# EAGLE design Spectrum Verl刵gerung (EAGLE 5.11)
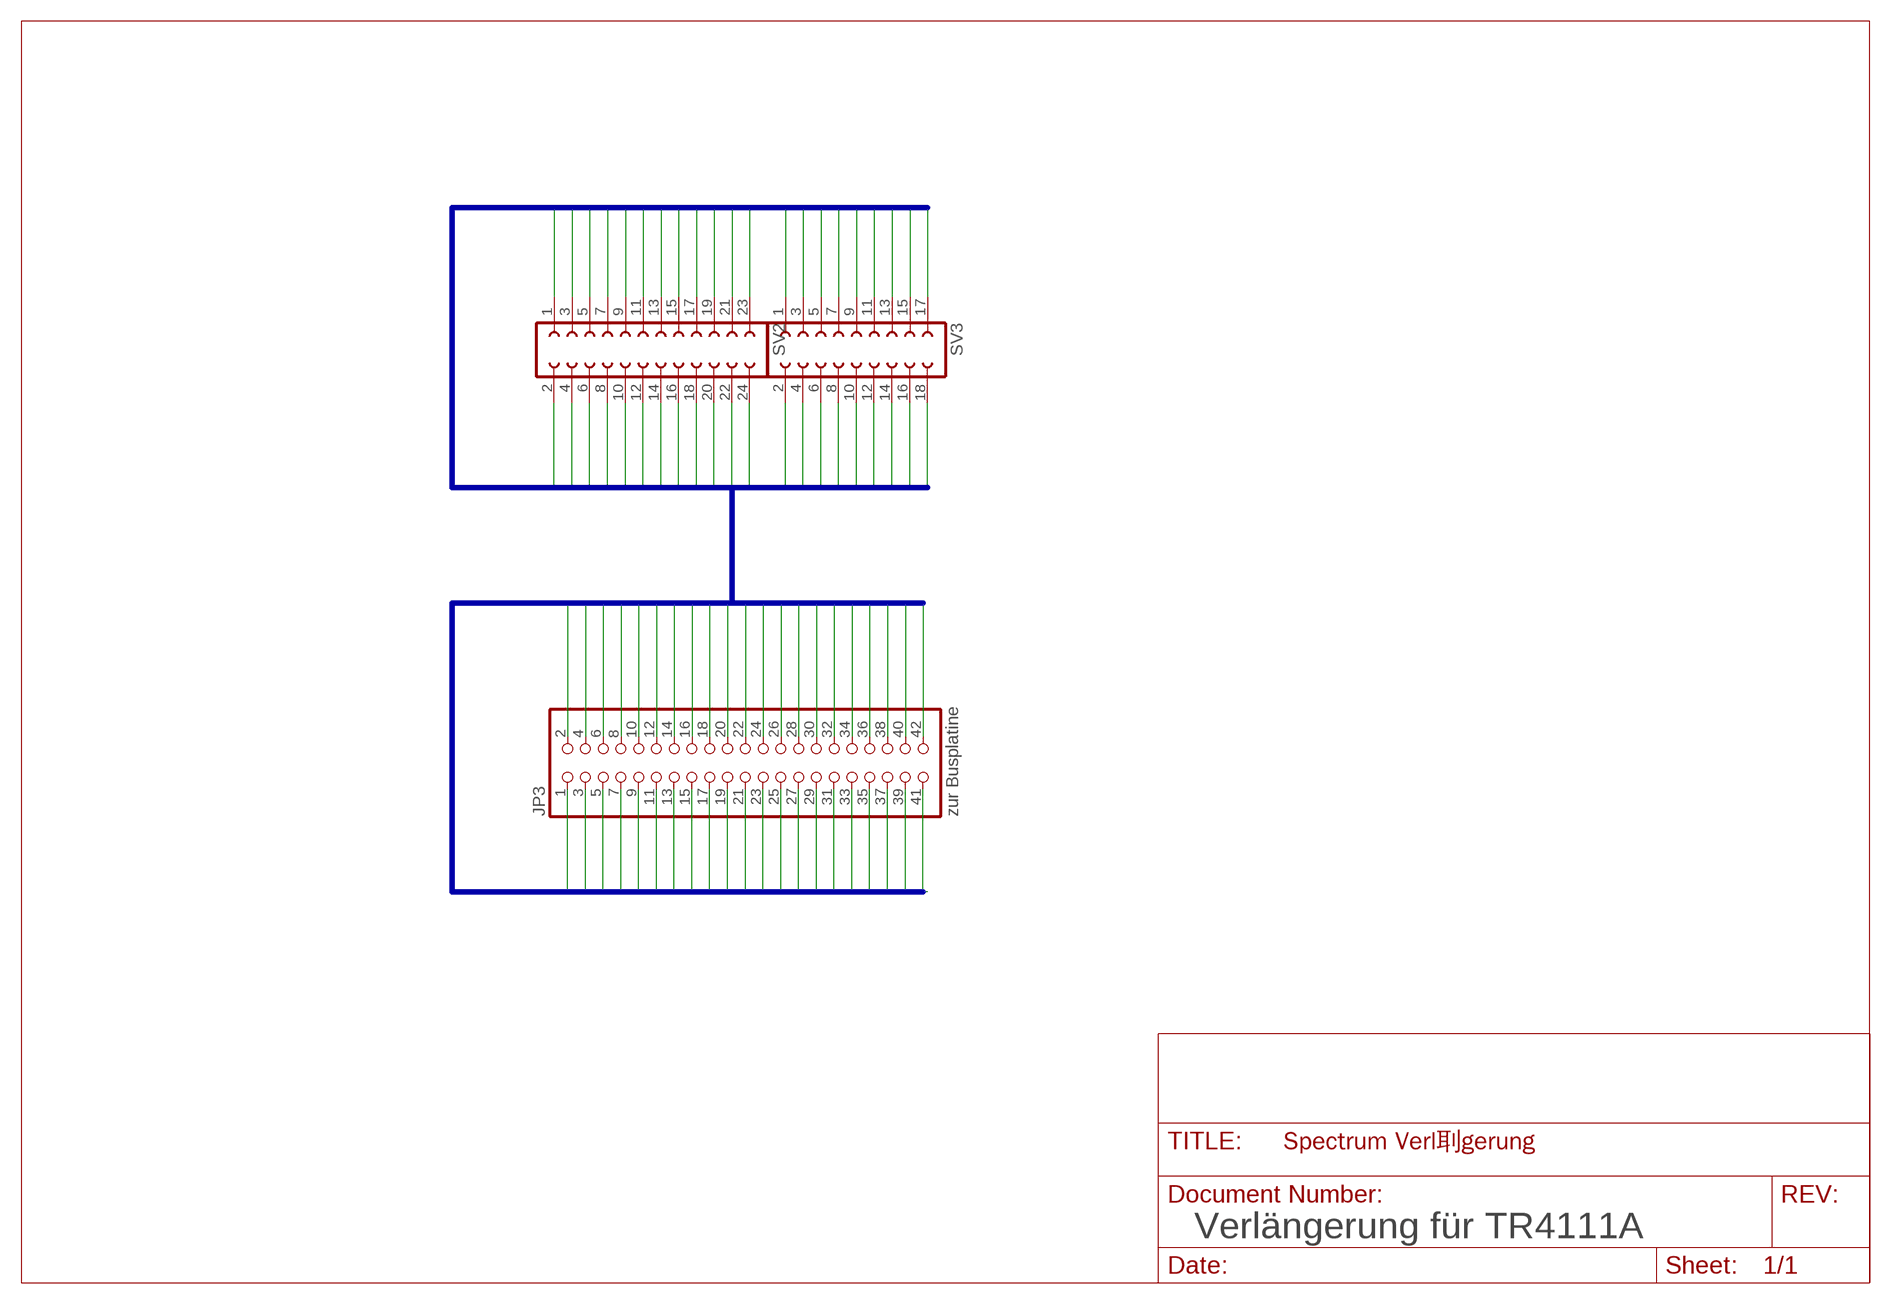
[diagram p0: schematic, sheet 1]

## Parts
JP3  zur Busplatine  PINHD-2X21_2.54-90°  [2X21/90]
SV2  FE12-2W  [FE12-2W]
SV3  FE09-2W  [FE09-2W]

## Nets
A1: JP3.1 SV2.1
A2: JP3.2 SV2.2
A3: JP3.3 SV2.3
A4: JP3.4 SV2.4
A5: JP3.5 SV2.5
A6: JP3.6 SV2.6
A7: JP3.7 SV2.7
A8: JP3.8 SV2.8
A9: JP3.9 SV2.9
A10: JP3.10 SV2.10
A11: JP3.11 SV2.11
A12: JP3.12 SV2.12
A13: JP3.13 SV2.13
A14: JP3.14 SV2.14
A15: JP3.15 SV2.15
A16: JP3.16 SV2.16
A17: JP3.17 SV2.17
A18: JP3.18 SV2.18
A19: JP3.19 SV2.19
A20: JP3.20 SV2.20
A21: JP3.21 SV2.21
A22: JP3.22 SV2.22
A23: JP3.23 SV2.23
A24: JP3.24 SV2.24
A25: JP3.25 SV3.1
A26: JP3.26 SV3.2
A27: JP3.27 SV3.3
A28: JP3.28 SV3.4
A29: JP3.29 SV3.5
A30: JP3.30 SV3.6
A31: JP3.31 SV3.7
A32: JP3.32 SV3.8
A33: JP3.33 SV3.9
A34: JP3.34 SV3.10
A35: JP3.35 SV3.11
A36: JP3.36 SV3.12
A37: JP3.37 SV3.13
A38: JP3.38 SV3.14
A39: JP3.39 SV3.15
A40: JP3.40 SV3.16
A41: JP3.41 SV3.17
A42: JP3.42 SV3.18

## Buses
A[1..42]

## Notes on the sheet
- Verlängerung für TR4111A

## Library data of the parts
JP3 = pinhead-2:PINHD-2X21: PIN HEADER
SV2 = con-lsta:FE12-2W: FEMALE HEADER
SV3 = con-lsta:FE09-2W: FEMALE HEADER

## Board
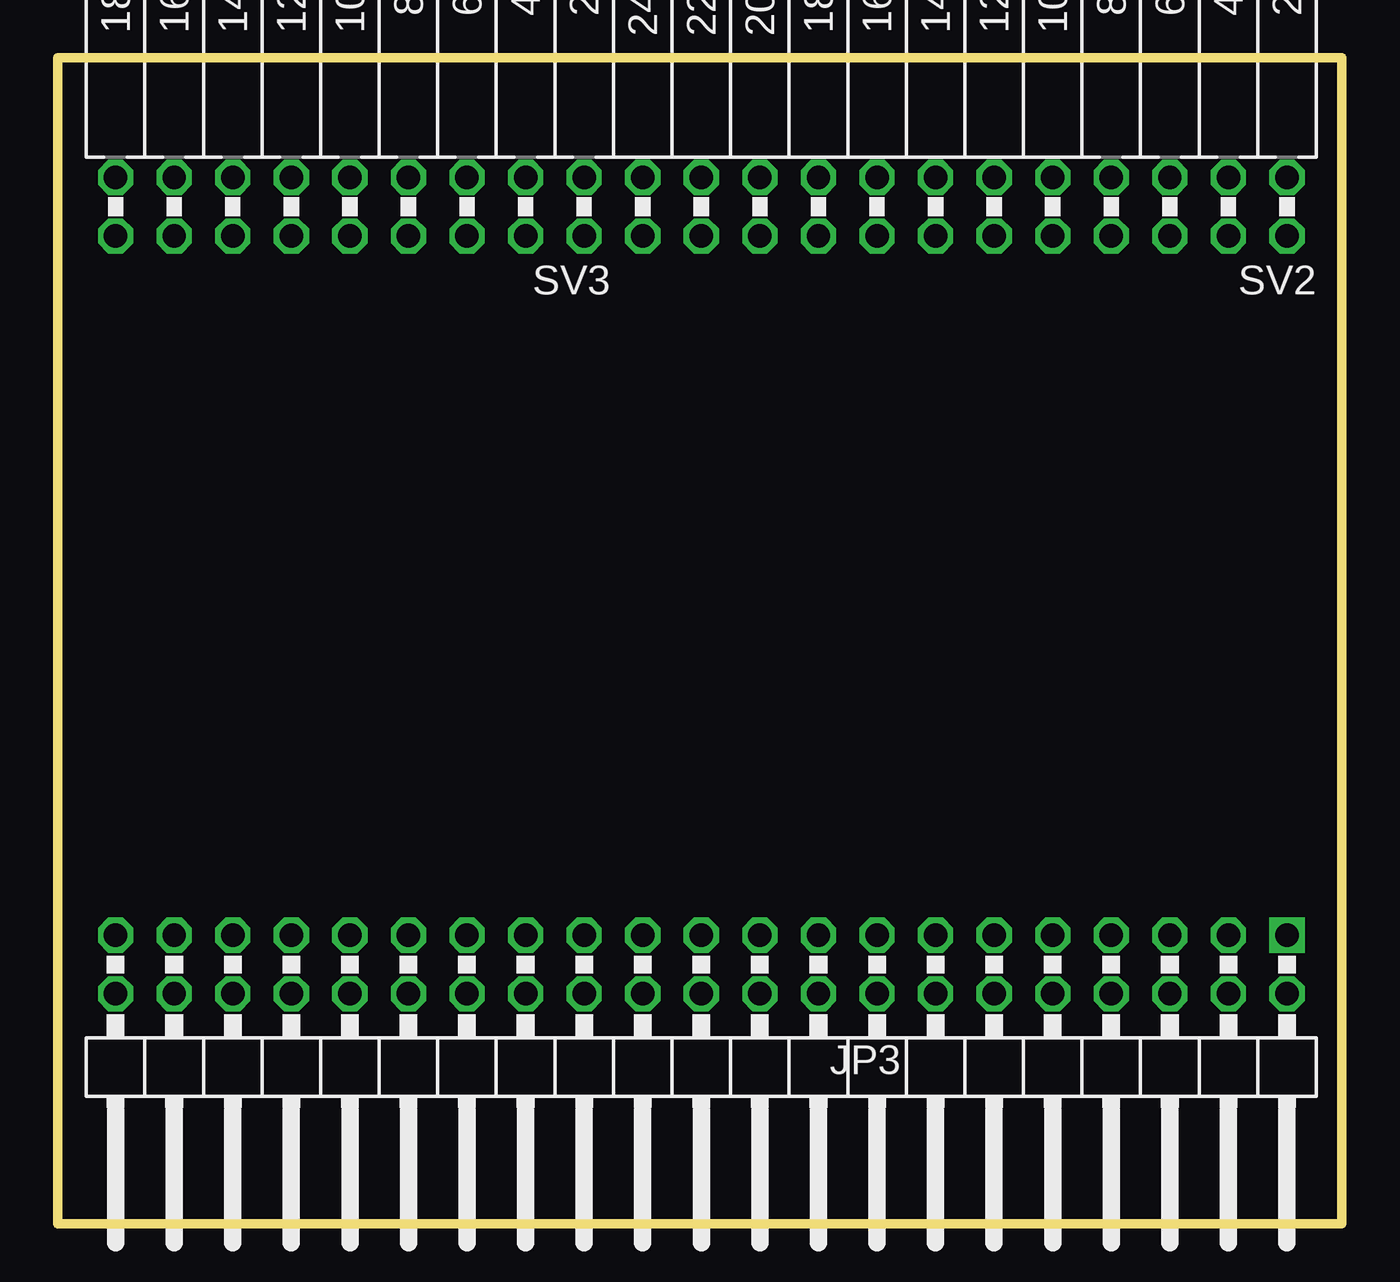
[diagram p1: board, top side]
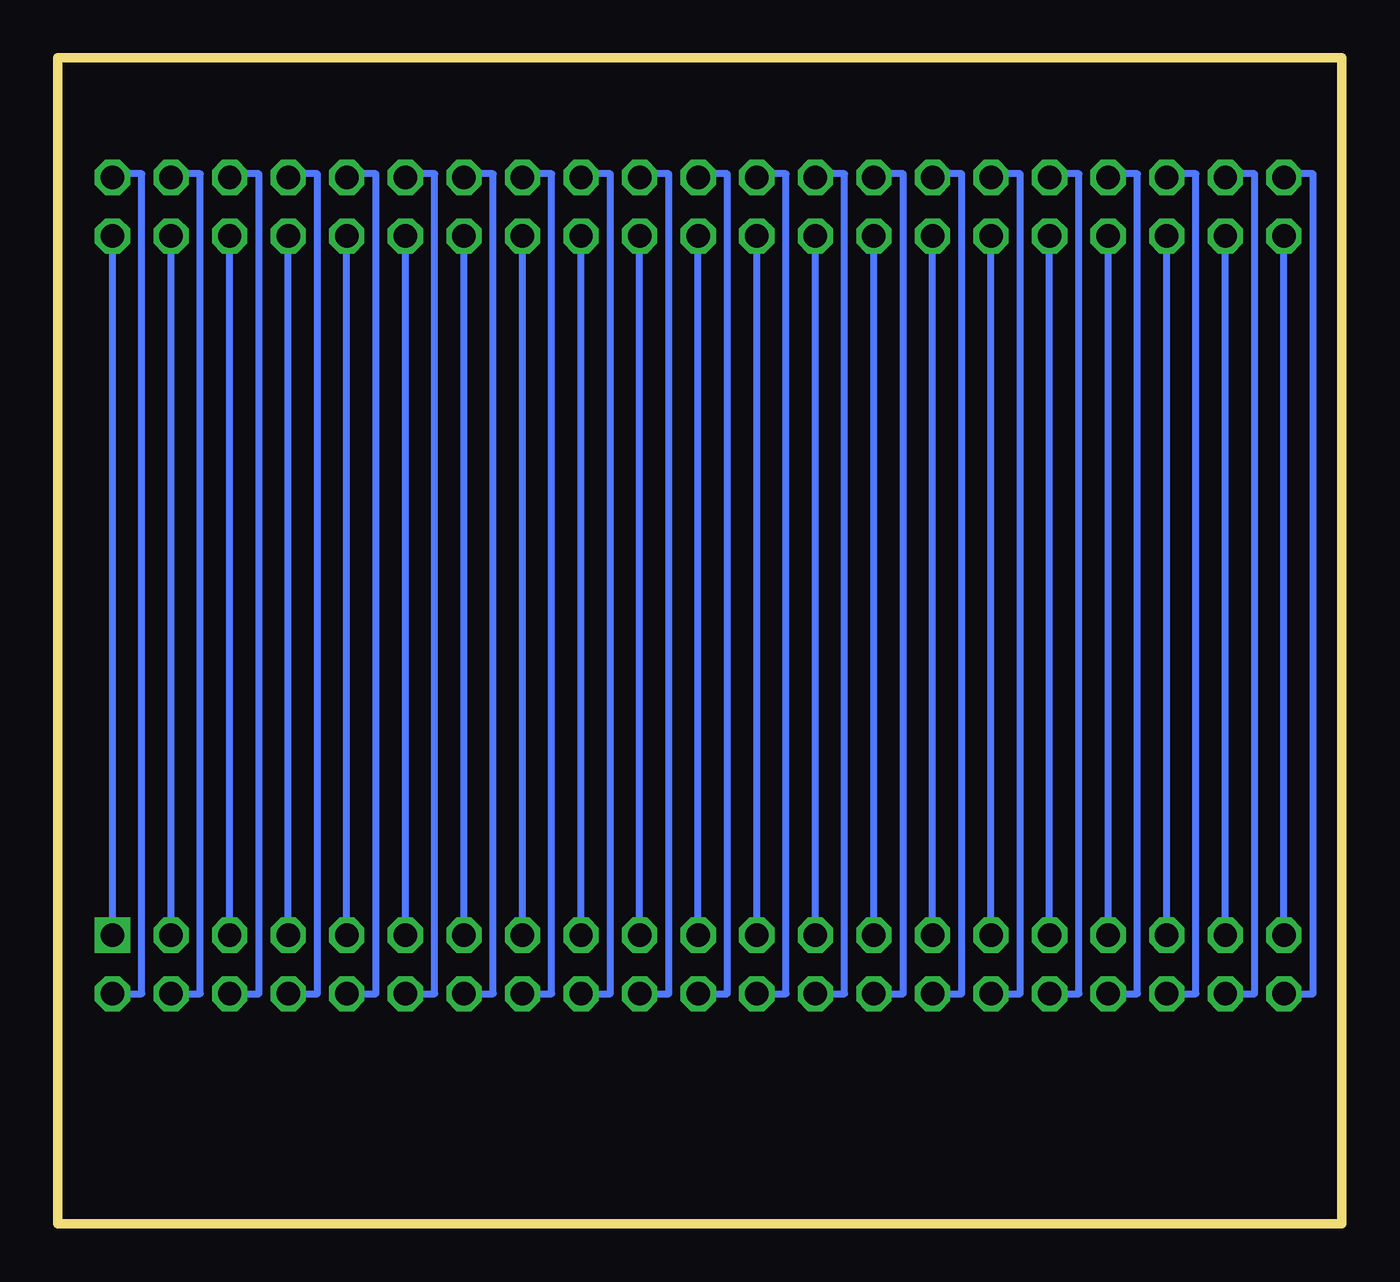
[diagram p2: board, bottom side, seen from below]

Size 55.69 x 50.58 mm. Coordinates in mm from the lower left corner, seen from the top.
Outline: 0,0 55.69,0 55.69,50.58 0,50.58 0,0
Copper layers (1*16): Top 0.035mm / dielectric 1.5mm / Bottom 0.035mm
Design rules "default *": minimum track width 0.2mm, minimum drill 0.6mm, track to track 0.3mm, track to pad 0.3mm, pad to pad 0.3mm, via to via 0.3mm, smd to smd 0.3mm, copper to edge 0mil, drill to drill 0.4mm, minimum pad ring 10mil, minimum via ring 10mil, stop-mask expansion 4mil, vias tented up to drill 0mil, thermal gap 10mil

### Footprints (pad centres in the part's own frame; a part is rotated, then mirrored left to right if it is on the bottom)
2X21/90 = drill 1.016 square: 1 -24.13,-6.35 | drill 1.016 octagon: 2 -24.13,-3.81; 3 -21.59,-6.35; 4 -21.59,-3.81; 5 -19.05,-6.35; 6 -19.05,-3.81; 7 -16.51,-6.35; 8 -16.51,-3.81; 9 -13.97,-6.35; 10 -13.97,-3.81; 11 -11.43,-6.35; 12 -11.43,-3.81; 13 -8.89,-6.35; 14 -8.89,-3.81; 15 -6.35,-6.35; 16 -6.35,-3.81; 17 -3.81,-6.35; 18 -3.81,-3.81; 19 -1.27,-6.35; 20 -1.27,-3.81; 21 1.27,-6.35; 22 1.27,-3.81; 23 3.81,-6.35; 24 3.81,-3.81; 25 6.35,-6.35; 26 6.35,-3.81; 27 8.89,-6.35; 28 8.89,-3.81; 29 11.43,-6.35; 30 11.43,-3.81; 31 13.97,-6.35; 32 13.97,-3.81; 33 16.51,-6.35; 34 16.51,-3.81; 35 19.05,-6.35; 36 19.05,-3.81; 37 21.59,-6.35; 38 21.59,-3.81; 39 24.13,-6.35; 40 24.13,-3.81; 41 26.67,-6.35; 42 26.67,-3.81
FE12-2W = drill 1.016 octagon: 1 -13.97,1.27; 2 -13.97,-1.27; 3 -11.43,1.27; 4 -11.43,-1.27; 5 -8.89,1.27; 6 -8.89,-1.27; 7 -6.35,1.27; 8 -6.35,-1.27; 9 -3.81,1.27; 10 -3.81,-1.27; 11 -1.27,1.27; 12 -1.27,-1.27; 13 1.27,1.27; 14 1.27,-1.27; 15 3.81,1.27; 16 3.81,-1.27; 17 6.35,1.27; 18 6.35,-1.27; 19 8.89,1.27; 20 8.89,-1.27; 21 11.43,1.27; 22 11.43,-1.27; 23 13.97,1.27; 24 13.97,-1.27
FE09-2W = drill 1.016 octagon: 1 -10.16,1.27; 2 -10.16,-1.27; 3 -7.62,1.27; 4 -7.62,-1.27; 5 -5.08,1.27; 6 -5.08,-1.27; 7 -2.54,1.27; 8 -2.54,-1.27; 9 0,1.27; 10 0,-1.27; 11 2.54,1.27; 12 2.54,-1.27; 13 5.08,1.27; 14 5.08,-1.27; 15 7.62,1.27; 16 7.62,-1.27; 17 10.16,1.27; 18 10.16,-1.27

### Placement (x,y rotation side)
JP3  29.18,6.17 180 top
SV2  39.34,44.11 180 top
SV3  12.67,44.11 180 top

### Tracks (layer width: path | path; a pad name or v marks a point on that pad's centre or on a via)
A1
  Bottom 0.305: JP3.1 | JP3.1 SV2.1
A2
  Bottom 0.305: JP3.2 52.04,9.98 52.04,45.54 53.31,45.54 SV2.2
A3
  Bottom 0.305: JP3.3 | JP3.3 SV2.3
A4
  Bottom 0.305: JP3.4 49.5,9.98 49.5,45.54 50.77,45.54 SV2.4
A5
  Bottom 0.305: JP3.5 | JP3.5 SV2.5
A6
  Bottom 0.305: JP3.6 46.96,9.98 46.96,45.54 48.23,45.54 SV2.6
A7
  Bottom 0.305: JP3.7 | JP3.7 SV2.7
A8
  Bottom 0.305: JP3.8 44.42,9.98 44.42,45.54 45.69,45.54 SV2.8
A9
  Bottom 0.305: JP3.9 | JP3.9 SV2.9
A10
  Bottom 0.305: JP3.10 41.88,9.98 41.88,45.54 43.15,45.54 SV2.10
A11
  Bottom 0.305: JP3.11 | JP3.11 SV2.11
A12
  Bottom 0.305: JP3.12 39.34,9.98 39.34,45.54 40.61,45.54 SV2.12
A13
  Bottom 0.305: JP3.13 | JP3.13 SV2.13
A14
  Bottom 0.305: JP3.14 36.8,9.98 36.8,45.54 38.07,45.54 SV2.14
A15
  Bottom 0.305: JP3.15 | JP3.15 SV2.15
A16
  Bottom 0.305: JP3.16 34.26,9.98 34.26,45.54 35.53,45.54 SV2.16
A17
  Bottom 0.305: JP3.17 | JP3.17 SV2.17
A18
  Bottom 0.305: JP3.18 31.72,9.98 31.72,45.54 32.99,45.54 SV2.18
A19
  Bottom 0.305: JP3.19 | JP3.19 SV2.19
A20
  Bottom 0.305: JP3.20 29.18,9.98 29.18,45.54 30.45,45.54 SV2.20
A21
  Bottom 0.305: JP3.21 | JP3.21 SV2.21
A22
  Bottom 0.305: JP3.22 26.64,9.98 26.64,45.54 27.91,45.54 SV2.22
A23
  Bottom 0.305: JP3.23 | JP3.23 SV2.23
A24
  Bottom 0.305: JP3.24 24.1,9.98 24.1,45.54 25.37,45.54 SV2.24
A25
  Bottom 0.305: JP3.25 SV3.1
A26
  Bottom 0.305: JP3.26 21.56,9.98 21.56,45.54 22.83,45.54 SV3.2
A27
  Bottom 0.305: JP3.27 SV3.3
A28
  Bottom 0.305: JP3.28 19.02,9.98 19.02,45.54 20.29,45.54 SV3.4
A29
  Bottom 0.305: JP3.29 SV3.5
A30
  Bottom 0.305: JP3.30 16.48,9.98 16.48,45.54 17.75,45.54 SV3.6
A31
  Bottom 0.305: JP3.31 SV3.7
A32
  Bottom 0.305: JP3.32 13.94,9.98 13.94,45.54 15.21,45.54 SV3.8
A33
  Bottom 0.305: JP3.33 SV3.9
A34
  Bottom 0.305: JP3.34 11.4,9.98 11.4,45.54 12.67,45.54 SV3.10
A35
  Bottom 0.305: JP3.35 SV3.11
A36
  Bottom 0.305: JP3.36 8.86,9.98 8.86,45.54 10.13,45.54 SV3.12
A37
  Bottom 0.305: JP3.37 SV3.13
A38
  Bottom 0.305: JP3.38 6.32,9.98 6.32,45.54 7.59,45.54 SV3.14
A39
  Bottom 0.305: JP3.39 SV3.15
A40
  Bottom 0.305: JP3.40 3.78,9.98 3.78,45.54 5.05,45.54 SV3.16
A41
  Bottom 0.305: JP3.41 SV3.17
A42
  Bottom 0.305: JP3.42 1.24,9.98 1.24,45.54 2.51,45.54 SV3.18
